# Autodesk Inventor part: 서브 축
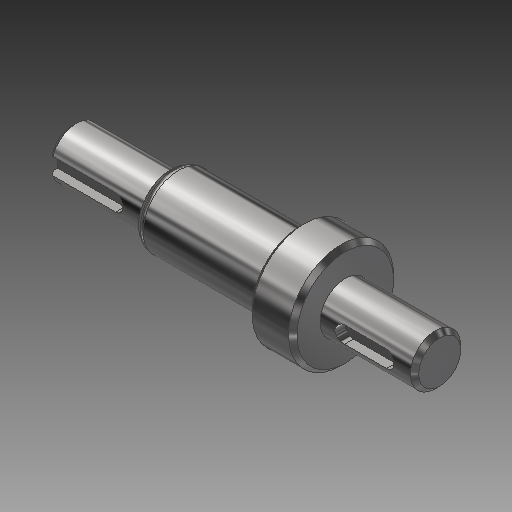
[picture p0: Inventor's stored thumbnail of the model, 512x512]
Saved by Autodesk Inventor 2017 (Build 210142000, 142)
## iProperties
Created: 2016-04
Part Number: 서브 축
Document SubType Name: Modeling
Designer: mdu
Density: 1 g/cm^3
Mass: 19.9624 g
Surface Area: 57.7178 cm^2
Volume: 19.9624 cm^3
Material: 강철, 연강
Appearance: 반광택
Author: mdu
Revision Number: 1
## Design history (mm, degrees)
sketch "스케치1"
  geometry: L1 (-16.331, 0)-(-103.831, 0); L2 (-16.331, 0)-(-16.331, -6); L3 (-16.331, -6)-(-38.831, -6); L4 (-38.831, -12.5)-(-46.5, -12.5); L5 (-46.5, -8.5)-(-79.013, -8.5); L6 (-103.831, -6)-(-103.831, 0); L7 (-46.5, -8.5)-(-46.5, -12.5); L8 (-38.831, -6)-(-38.831, -12.5); L9 (-46.5, 12.249)-(-46.5, -12.249) reference; L10 (-38.831, -17)-(-38.831, 17) reference; L11 (-103.831, -6)-(-80.831, -6); L12 (-80.831, -6)-(-80.831, -7.45); L13 (-80.831, -7.45)-(-79.013, -8.5); 2 further points
  constraints: 23 end point, 6 perpendicular, 2 collinear, 2 parallel, 1 horizontal, 1 midpoint, 1 point on line
  dimensions: "d1" = 12 diameter of L3 L1; "d2" = 25 diameter of L4 L1; "d3" = 17 diameter of L5 L1; "d18" = 22.5 distance of L2.end L3.end; "d20" = 65 distance between parallel lines of L6 L8; "d21" = 7.66872 distance of L4.start L4.end (derived); "d28" = 12 diameter of L11 L1; "d29" = 23 distance of L6.start L11.end; "d30" = 14.9 diameter of L12.end L1; "d32" = 30 deg angle of L5 L13
revolve "회전1" sketch "스케치1" stored, may be unused: angle "d5" = 90 deg
chamfer "모따기1" distance "d6" = 1; stored, may be unused: second distance "d7" = 2, angle "d8" = 45 deg
node "작업 평면1"
sketch "스케치2"
  geometry: L1 (11.25, 5)-(11.25, -5) reference; L2 (-5.75, -2)-(4.25, -2); L3 (4.25, 2)-(-5.75, 2); A1 r 2 centre (4.25, 0) between (4.25, -2) and (4.25, 2); A2 r 2 centre (-5.75, 0) between (-5.75, 2) and (-5.75, -2); 2 further points
  constraints: 4 end point, 4 point on circle, 4 tangent, 2 centre point, 1 horizontal alignment, 1 midpoint, 1 parallel, 1 perpendicular
  dimensions: "d9" = 4 distance between parallel lines of L2 L3; "d10" = 14 dimension on A1 A2; "d11" = 5 distance edge to line of A1 L1
extrude "돌출1" cut sketch "스케치2" distance "d12" = 2.5; taper "d13" = 0 deg
node "작업 평면2"
sketch "스케치3"
  geometry: L1 (-103.831, -5)-(-103.831, 5) reference; L2 (-103.831, 2)-(-87.831, 2); L3 (-87.831, -2)-(-103.831, -2); A1 r 2 centre (-87.831, 0) between (-87.831, -2) and (-87.831, 2); 2 further points
  constraints: 4 end point, 2 perpendicular, 2 point on circle, 2 point on line, 2 tangent, 1 centre point, 1 horizontal alignment, 1 midpoint
  dimensions: "d14" = 4 distance between parallel lines of L3 L2; "d15" = 18 dimension on A1 L1
extrude "돌출2" cut sketch "스케치3" distance "d16" = 2.5; taper "d17" = 0 deg
sketch "스케치4"
  geometry: C1 r 12.5 at (0, 0) reference; 1 further point
extrude "돌출3" join sketch "스케치4" distance "d22" = 3; taper "d23" = 0 deg
chamfer "모따기2" distance "d24" = 1; stored, may be unused: second distance "d25" = 2, angle "d26" = 45 deg
fillet "모깎기1" dims "d34" = 1
fillet "모깎기2" dims "d35" = 2
node "솔리드1"
node "참조4"
node "참조5"
other parameters: "d33" = 6
